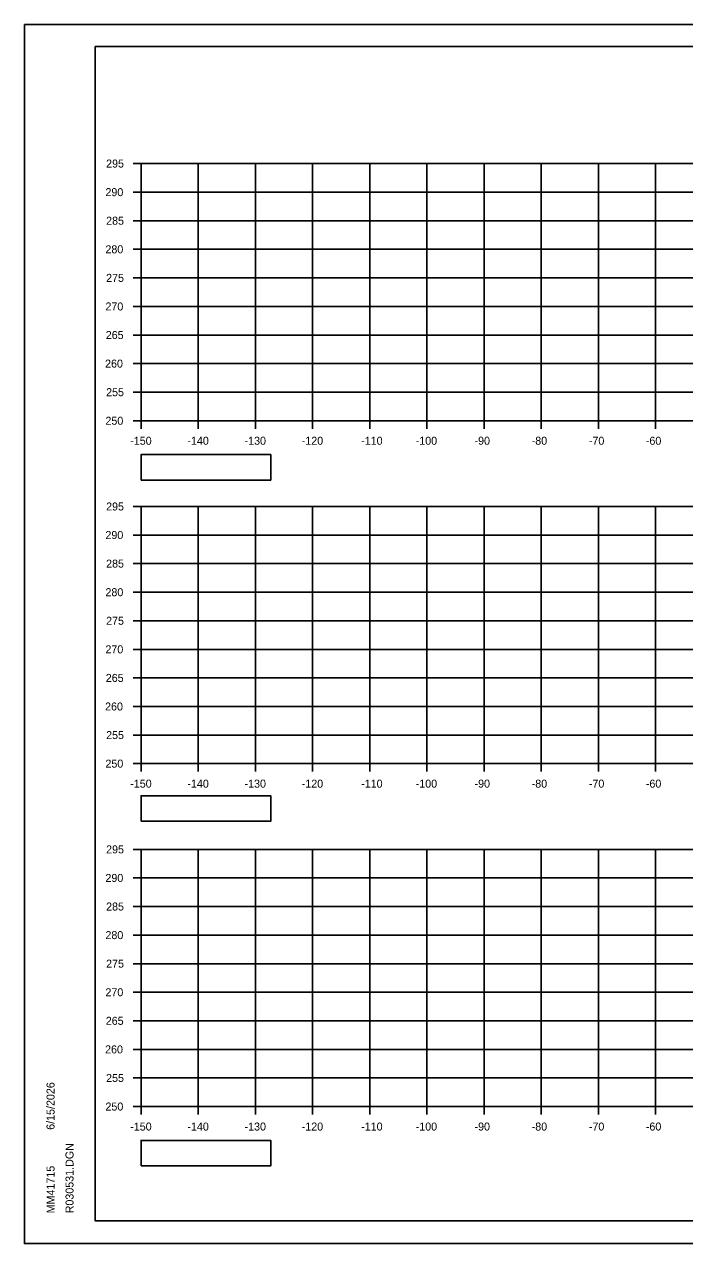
# Model space of a CAD drawing. Extents: x 285 to 4233, y -659 to 3710.
# Drawn here: x 3900 to 4015.5, y -365.9 to -152.6 of the extents above; entities that cross this region are included whole.
import ezdxf

# ---------------------------------------------------------------- set-up
doc = ezdxf.new("R2010")
doc.units = 0
for name, color, linetype in [('R_Axis', 7, 'Continuous'), ('R_Axis Annot', 7, 'Continuous'), ('R_Border', 7, 'Continuous'), ('R_Grid', 7, 'Continuous'), ('R_No Plot', 7, 'Continuous')]:
    doc.layers.add(name, color=color, linetype=linetype)

msp = doc.modelspace()

# ---------------------------------------------------------------- linework, layer by layer
at = {"layer": 'R_Axis'}
for p, q in [((3918.98, -176.92), (3920.38, -176.92)), ((3920.38, -221.92), (3920.38, -176.92)), ((3918.98, -181.92), (3920.38, -181.92)), ((3918.98, -186.92), (3920.38, -186.92)), ((3918.98, -191.92), (3920.38, -191.92)), ((3918.98, -196.92), (3920.38, -196.92)), ((3918.98, -201.92), (3920.38, -201.92)), ((3918.98, -206.92), (3920.38, -206.92)), ((3918.98, -211.92), (3920.38, -211.92)), ((3918.98, -216.92), (3920.38, -216.92)), ((3918.98, -221.92), (3920.38, -221.92)), ((3920.38, -221.92), (4220.38, -221.92)), ((3920.38, -223.32), (3920.38, -221.92)), ((3930.38, -223.32), (3930.38, -221.92)), ((3940.38, -223.32), (3940.38, -221.92)), ((3950.38, -223.32), (3950.38, -221.92)), ((3960.38, -223.32), (3960.38, -221.92)), ((3970.38, -223.32), (3970.38, -221.92)), ((3980.38, -223.32), (3980.38, -221.92)), ((3990.38, -223.32), (3990.38, -221.92)), ((4000.38, -223.32), (4000.38, -221.92)), ((4010.38, -223.32), (4010.38, -221.92)), ((3918.98, -236.92), (3920.38, -236.92)), ((3920.38, -281.92), (3920.38, -236.92)), ((3918.98, -241.92), (3920.38, -241.92)), ((3918.98, -246.92), (3920.38, -246.92)), ((3918.98, -251.92), (3920.38, -251.92)), ((3918.98, -256.92), (3920.38, -256.92)), ((3918.98, -261.92), (3920.38, -261.92)), ((3918.98, -266.92), (3920.38, -266.92)), ((3918.98, -271.92), (3920.38, -271.92)), ((3918.98, -276.92), (3920.38, -276.92)), ((3918.98, -281.92), (3920.38, -281.92)), ((3920.38, -281.92), (4220.38, -281.92)), ((3920.38, -283.32), (3920.38, -281.92)), ((3930.38, -283.32), (3930.38, -281.92)), ((3940.38, -283.32), (3940.38, -281.92)), ((3950.38, -283.32), (3950.38, -281.92)), ((3960.38, -283.32), (3960.38, -281.92)), ((3970.38, -283.32), (3970.38, -281.92)), ((3980.38, -283.32), (3980.38, -281.92)), ((3990.38, -283.32), (3990.38, -281.92)), ((4000.38, -283.32), (4000.38, -281.92)), ((4010.38, -283.32), (4010.38, -281.92)), ((3918.98, -296.92), (3920.38, -296.92)), ((3920.38, -341.92), (3920.38, -296.92)), ((3918.98, -301.92), (3920.38, -301.92)), ((3918.98, -306.92), (3920.38, -306.92)), ((3918.98, -311.92), (3920.38, -311.92)), ((3918.98, -316.92), (3920.38, -316.92)), ((3918.98, -321.92), (3920.38, -321.92)), ((3918.98, -326.92), (3920.38, -326.92)), ((3918.98, -331.92), (3920.38, -331.92)), ((3918.98, -336.92), (3920.38, -336.92)), ((3918.98, -341.92), (3920.38, -341.92)), ((3920.38, -341.92), (4220.38, -341.92)), ((3920.38, -343.32), (3920.38, -341.92)), ((3930.38, -343.32), (3930.38, -341.92)), ((3940.38, -343.32), (3940.38, -341.92)), ((3950.38, -343.32), (3950.38, -341.92)), ((3960.38, -343.32), (3960.38, -341.92)), ((3970.38, -343.32), (3970.38, -341.92)), ((3980.38, -343.32), (3980.38, -341.92)), ((3990.38, -343.32), (3990.38, -341.92)), ((4000.38, -343.32), (4000.38, -341.92)), ((4010.38, -343.32), (4010.38, -341.92))]:
    msp.add_line(p, q, dxfattribs=at)
at = {"layer": 'R_Axis Annot'}
for points in [[(3920.38, -232.31), (3943.08, -232.31), (3943.08, -227.85), (3920.38, -227.85)], [(3920.38, -292.01), (3943.08, -292.01), (3943.08, -287.55), (3920.38, -287.55)], [(3920.38, -352.32), (3943.08, -352.32), (3943.08, -347.85), (3920.38, -347.85)]]:
    msp.add_lwpolyline(points, close=True, dxfattribs=at)
at = {"layer": 'R_Border'}
for p, q in [((3912.38, -156.46), (4228.56, -156.46)), ((3912.38, -361.92), (3912.38, -156.46)), ((3912.38, -361.92), (3912.38, -361.92)), ((4228.56, -361.92), (3912.38, -361.92))]:
    msp.add_line(p, q, dxfattribs=at)
at = {"layer": 'R_Grid'}
for p, q in [((3920.38, -176.92), (4220.38, -176.92)), ((3920.38, -221.92), (3920.38, -176.92)), ((3930.38, -221.92), (3930.38, -176.92)), ((3940.38, -221.92), (3940.38, -176.92)), ((3950.38, -221.92), (3950.38, -176.92)), ((3960.38, -221.92), (3960.38, -176.92)), ((3970.38, -221.92), (3970.38, -176.92)), ((3980.38, -221.92), (3980.38, -176.92)), ((3990.38, -221.92), (3990.38, -176.92)), ((4000.38, -221.92), (4000.38, -176.92)), ((4010.38, -221.92), (4010.38, -176.92)), ((3920.38, -181.92), (4220.38, -181.92)), ((3920.38, -186.92), (4220.38, -186.92)), ((3920.38, -191.92), (4220.38, -191.92)), ((3920.38, -196.92), (4220.38, -196.92)), ((3920.38, -201.92), (4220.38, -201.92)), ((3920.38, -206.92), (4220.38, -206.92)), ((3920.38, -211.92), (4220.38, -211.92)), ((3920.38, -216.92), (4220.38, -216.92)), ((3920.38, -221.92), (4220.38, -221.92)), ((3920.38, -236.92), (4220.38, -236.92)), ((3920.38, -281.92), (3920.38, -236.92)), ((3930.38, -281.92), (3930.38, -236.92)), ((3940.38, -281.92), (3940.38, -236.92)), ((3950.38, -281.92), (3950.38, -236.92)), ((3960.38, -281.92), (3960.38, -236.92)), ((3970.38, -281.92), (3970.38, -236.92)), ((3980.38, -281.92), (3980.38, -236.92)), ((3990.38, -281.92), (3990.38, -236.92)), ((4000.38, -281.92), (4000.38, -236.92)), ((4010.38, -281.92), (4010.38, -236.92)), ((3920.38, -241.92), (4220.38, -241.92)), ((3920.38, -246.92), (4220.38, -246.92)), ((3920.38, -251.92), (4220.38, -251.92)), ((3920.38, -256.92), (4220.38, -256.92)), ((3920.38, -261.92), (4220.38, -261.92)), ((3920.38, -266.92), (4220.38, -266.92)), ((3920.38, -271.92), (4220.38, -271.92)), ((3920.38, -276.92), (4220.38, -276.92)), ((3920.38, -281.92), (4220.38, -281.92)), ((3920.38, -296.92), (4220.38, -296.92)), ((3920.38, -341.92), (3920.38, -296.92)), ((3930.38, -341.92), (3930.38, -296.92)), ((3940.38, -341.92), (3940.38, -296.92)), ((3950.38, -341.92), (3950.38, -296.92)), ((3960.38, -341.92), (3960.38, -296.92)), ((3970.38, -341.92), (3970.38, -296.92)), ((3980.38, -341.92), (3980.38, -296.92)), ((3990.38, -341.92), (3990.38, -296.92)), ((4000.38, -341.92), (4000.38, -296.92)), ((4010.38, -341.92), (4010.38, -296.92)), ((3920.38, -301.92), (4220.38, -301.92)), ((3920.38, -306.92), (4220.38, -306.92)), ((3920.38, -311.92), (4220.38, -311.92)), ((3920.38, -316.92), (4220.38, -316.92)), ((3920.38, -321.92), (4220.38, -321.92)), ((3920.38, -326.92), (4220.38, -326.92)), ((3920.38, -331.92), (4220.38, -331.92)), ((3920.38, -336.92), (4220.38, -336.92)), ((3920.38, -341.92), (4220.38, -341.92))]:
    msp.add_line(p, q, dxfattribs=at)
at = {"layer": 'R_No Plot'}
for p, q in [((3899.98, -152.57), (4233.31, -152.57)), ((3899.98, -365.9), (4233.31, -365.9))]:
    msp.add_line(p, q, dxfattribs=at)
for points in [[(3899.97, -152.57), (4233.31, -152.57), (4233.31, -365.9), (3899.97, -365.9)], [(4146.3, -156.46), (4165.92, -156.46), (4165.92, -166.34), (4182.03, -166.34), (4205.23, -166.34), (4205.35, -194.5), (4228.56, -194.5), (4228.56, -361.92), (3912.38, -361.92), (3912.38, -156.46)]]:
    msp.add_lwpolyline(points, close=True, dxfattribs=at)

# ---------------------------------------------------------------- texts
at = {"layer": 'R_Axis Annot'}
for s, p in [('295', (3914.27, -177.62)), ('290', (3914.15, -182.62)), ('285', (3914.27, -187.62)), ('280', (3914.15, -192.62)), ('275', (3914.27, -197.62)), ('270', (3914.15, -202.62)), ('265', (3914.21, -207.62)), ('260', (3914.09, -212.62)), ('255', (3914.27, -217.62)), ('250', (3914.15, -222.62)), ('-150', (3918.49, -226.12)), ('-140', (3928.49, -226.12)), ('-130', (3938.49, -226.12)), ('-120', (3948.49, -226.12)), ('-110', (3958.89, -226.12)), ('-100', (3968.43, -226.12)), ('-90', (3978.72, -226.12)), ('-80', (3988.72, -226.12)), ('-70', (3998.72, -226.12)), ('-60', (4008.69, -226.12)), ('295', (3914.27, -237.62)), ('290', (3914.15, -242.62)), ('285', (3914.27, -247.62)), ('280', (3914.15, -252.62)), ('275', (3914.27, -257.62)), ('270', (3914.15, -262.62)), ('265', (3914.21, -267.62)), ('260', (3914.09, -272.62)), ('255', (3914.27, -277.62)), ('250', (3914.15, -282.62)), ('-150', (3918.49, -286.12)), ('-140', (3928.49, -286.12)), ('-130', (3938.49, -286.12)), ('-120', (3948.49, -286.12)), ('-110', (3958.89, -286.12)), ('-100', (3968.43, -286.12)), ('-90', (3978.72, -286.12)), ('-80', (3988.72, -286.12)), ('-70', (3998.72, -286.12)), ('-60', (4008.69, -286.12)), ('295', (3914.27, -297.62)), ('290', (3914.15, -302.62)), ('285', (3914.27, -307.62)), ('280', (3914.15, -312.62)), ('275', (3914.27, -317.62)), ('270', (3914.15, -322.62)), ('265', (3914.21, -327.62)), ('260', (3914.09, -332.62)), ('255', (3914.27, -337.62)), ('250', (3914.15, -342.62)), ('-150', (3918.49, -346.12)), ('-140', (3928.49, -346.12)), ('-130', (3938.49, -346.12)), ('-120', (3948.49, -346.12)), ('-110', (3958.89, -346.12)), ('-100', (3968.43, -346.12)), ('-90', (3978.72, -346.12)), ('-80', (3988.72, -346.12)), ('-70', (3998.72, -346.12)), ('-60', (4008.69, -346.12))]:
    msp.add_text(s, height=1.4, dxfattribs=at).set_placement(p)
at = {"layer": 'R_Border'}
for s, p in [('6/15/2026', (3905.25, -345.99)), ('R030531.DGN', (3908.57, -360.6)), ('MM41715', (3905.25, -360.6))]:
    msp.add_text(s, height=1.4, rotation=90, dxfattribs=at).set_placement(p)

doc.saveas('drawing.dxf')
